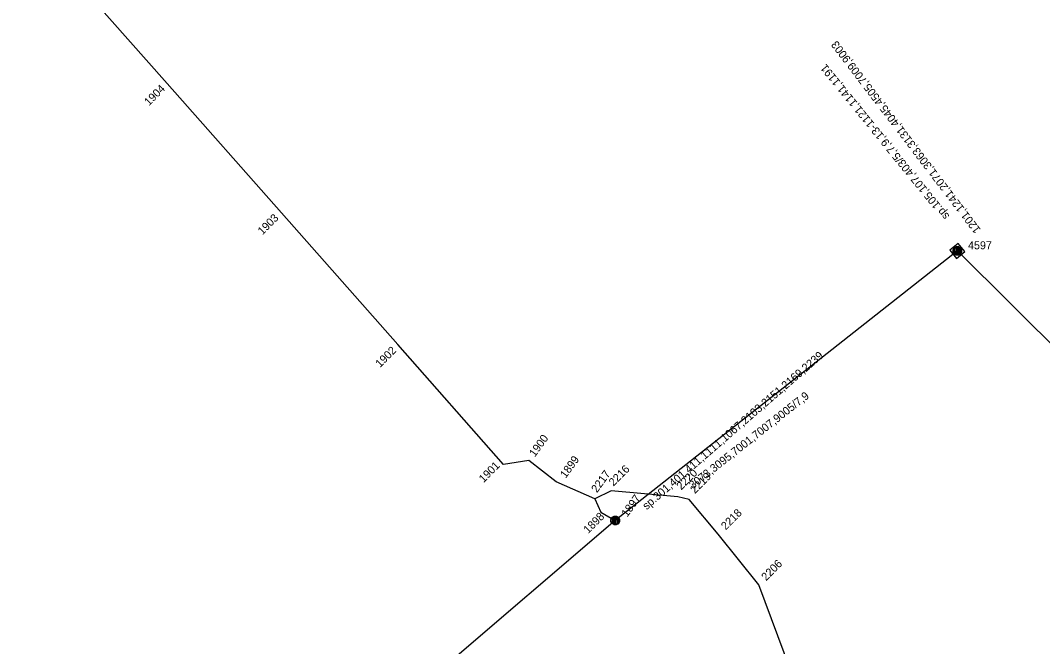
# Model space of a CAD drawing. Extents: x -535557 to -534097, y -1142175 to -1136716.
# Drawn here: x -534616.6 to -534520.9, y -1139282 to -1139223.4 of the extents above; entities that cross this region are included whole.
import ezdxf

# ---------------------------------------------------------------- set-up
doc = ezdxf.new("R2010")
doc.units = 0
doc.layers.add('Default', color=7, linetype='Continuous')
doc.layers.add('SS_SZDC', color=7, linetype='Continuous')

# ---------------------------------------------------------------- blocks, each defined once
blk = doc.blocks.new('POINT_DISPLAY')
at = {"layer": 'Default'}
blk.add_line((0, 0), (0, 0), dxfattribs=at)

msp = doc.modelspace()

# ---------------------------------------------------------------- linework, layer by layer
at = {"layer": 'SS_SZDC'}
for p, q in [((-534602.909, -1139229.299), (-534613.649, -1139217.11)), ((-534592.17, -1139241.399), (-534602.909, -1139229.299)), ((-534581.3, -1139253.739), (-534592.17, -1139241.399)), ((-534528.869, -1139244.969), (-534560.92, -1139270.209)), ((-534528.803, -1139244.266), (-534529.573, -1139244.903)), ((-534529.573, -1139244.903), (-534528.936, -1139245.673)), ((-534529.27, -1139245.066), (-534529.269, -1139244.866)), ((-534529.269, -1139244.866), (-534529.167, -1139244.667)), ((-534529.168, -1139244.817), (-534529.171, -1139245.117)), ((-534529.167, -1139244.667), (-534528.966, -1139244.569)), ((-534529.072, -1139245.268), (-534529.067, -1139244.718)), ((-534529.067, -1139244.718), (-534528.966, -1139244.619)), ((-534528.966, -1139244.619), (-534528.973, -1139245.319)), ((-534528.966, -1139244.569), (-534528.766, -1139244.57)), ((-534528.873, -1139245.319), (-534528.866, -1139244.62)), ((-534507.189, -1139266.5), (-534528.869, -1139244.969)), ((-534528.166, -1139245.036), (-534528.803, -1139244.266)), ((-534528.773, -1139245.32), (-534528.766, -1139244.62)), ((-534528.766, -1139244.57), (-534528.567, -1139244.672)), ((-534528.766, -1139244.62), (-534528.667, -1139244.721)), ((-534528.667, -1139244.721), (-534528.672, -1139245.271)), ((-534528.571, -1139245.122), (-534528.568, -1139244.822)), ((-534528.567, -1139244.672), (-534528.469, -1139244.873)), ((-534528.469, -1139244.873), (-534528.47, -1139245.073)), ((-534529.172, -1139245.267), (-534529.27, -1139245.066)), ((-534528.973, -1139245.369), (-534529.172, -1139245.267)), ((-534529.171, -1139245.117), (-534529.072, -1139245.268)), ((-534528.973, -1139245.319), (-534528.773, -1139245.32)), ((-534528.773, -1139245.37), (-534528.973, -1139245.369)), ((-534528.936, -1139245.673), (-534528.166, -1139245.036)), ((-534528.572, -1139245.272), (-534528.773, -1139245.37)), ((-534528.672, -1139245.271), (-534528.571, -1139245.122)), ((-534528.47, -1139245.073), (-534528.572, -1139245.272)), ((-534571.399, -1139264.959), (-534581.3, -1139253.739)), ((-534569.01, -1139264.61), (-534571.399, -1139264.959)), ((-534566.439, -1139266.6), (-534569.01, -1139264.61)), ((-534562.829, -1139268.18), (-534566.439, -1139266.6)), ((-534561.31, -1139267.44), (-534562.829, -1139268.18)), ((-534555.06, -1139268), (-534561.31, -1139267.44)), ((-534562.829, -1139268.18), (-534562.27, -1139269.43)), ((-534553.989, -1139268.239), (-534555.06, -1139268)), ((-534551.27, -1139271.489), (-534553.989, -1139268.239)), ((-534562.27, -1139269.43), (-534560.92, -1139270.209)), ((-534561.319, -1139270.106), (-534561.217, -1139269.907)), ((-534561.217, -1139269.907), (-534561.016, -1139269.809)), ((-534561.117, -1139269.958), (-534561.016, -1139269.859)), ((-534561.016, -1139269.859), (-534561.023, -1139270.559)), ((-534561.016, -1139269.809), (-534560.816, -1139269.81)), ((-534560.923, -1139270.559), (-534560.916, -1139269.86)), ((-534560.823, -1139270.56), (-534560.816, -1139269.86)), ((-534560.816, -1139269.81), (-534560.617, -1139269.912)), ((-534560.816, -1139269.86), (-534560.717, -1139269.961)), ((-534560.92, -1139270.209), (-534616.64, -1139317.829)), ((-534561.32, -1139270.306), (-534561.319, -1139270.106)), ((-534561.222, -1139270.507), (-534561.32, -1139270.306)), ((-534561.023, -1139270.609), (-534561.222, -1139270.507)), ((-534561.218, -1139270.057), (-534561.221, -1139270.357)), ((-534561.221, -1139270.357), (-534561.122, -1139270.508)), ((-534561.122, -1139270.508), (-534561.117, -1139269.958)), ((-534561.023, -1139270.559), (-534560.823, -1139270.56)), ((-534560.823, -1139270.61), (-534561.023, -1139270.609)), ((-534560.622, -1139270.512), (-534560.823, -1139270.61)), ((-534560.717, -1139269.961), (-534560.722, -1139270.511)), ((-534560.722, -1139270.511), (-534560.621, -1139270.362)), ((-534560.52, -1139270.313), (-534560.622, -1139270.512)), ((-534560.621, -1139270.362), (-534560.618, -1139270.062)), ((-534560.617, -1139269.912), (-534560.519, -1139270.113)), ((-534560.519, -1139270.113), (-534560.52, -1139270.313)), ((-534547.47, -1139276.239), (-534551.27, -1139271.489)), ((-534542.529, -1139289.43), (-534547.47, -1139276.239))]:
    msp.add_line(p, q, dxfattribs=at)

# ---------------------------------------------------------------- block references
for p in [(-534602.909, -1139229.299), (-534592.17, -1139241.399), (-534528.869, -1139244.969), (-534581.3, -1139253.739), (-534571.399, -1139264.959), (-534569.01, -1139264.61), (-534566.439, -1139266.6), (-534561.31, -1139267.44), (-534562.829, -1139268.18), (-534555.06, -1139268), (-534553.989, -1139268.239), (-534562.27, -1139269.43), (-534560.92, -1139270.209), (-534551.27, -1139271.489), (-534547.47, -1139276.239)]:
    msp.add_blockref('POINT_DISPLAY', p, dxfattribs=at)

# ---------------------------------------------------------------- texts
for s, height, rotation, p in [('1201,1241,2071,3063,3131,4045,4505,7009,9003', 0.74999, 127.27566, (-534526.645, -1139242.976)), ('sp.105,107,403/5,7,9,13-1121,1141,1191', 0.74999, 129.07566, (-534529.581, -1139241.694)), ('1904', 0.75, 45, (-534604.601, -1139231.428)), ('1903', 0.75, 45, (-534593.971, -1139243.527)), ('1902', 0.75, 45, (-534582.946, -1139255.944)), ('sp.301,401,411,1111,1067,2103,2151,2169,2239', 0.74999, 40.87566, (-534557.979, -1139269.256)), ('3073,3095,7001,7007,9005/7,9', 0.74999, 38.17566, (-534553.649, -1139267.299)), ('1900', 0.75, 54, (-534568.45, -1139264.319)), ('1901', 0.75, 45, (-534573.251, -1139266.716)), ('1899', 0.75, 54, (-534565.561, -1139266.31)), ('2216', 0.75, 45, (-534561.083, -1139267.053)), ('2217', 0.75, 54, (-534562.632, -1139267.667)), ('2220', 0.75, 45, (-534554.734, -1139267.411)), ('2219', 0.75, 45, (-534553.45, -1139267.746)), ('1897', 0.75, 54, (-534559.802, -1139269.949)), ('1898', 0.75, 45, (-534563.455, -1139271.49)), ('2218', 0.75, 45, (-534550.567, -1139271.15)), ('2206', 0.75, 45, (-534546.79, -1139275.913))]:
    msp.add_text(s, height=height, rotation=rotation, dxfattribs=at).set_placement(p)
msp.add_text('4597', height=0.75, dxfattribs=at).set_placement((-534527.869, -1139244.819))

doc.saveas('drawing.dxf')
